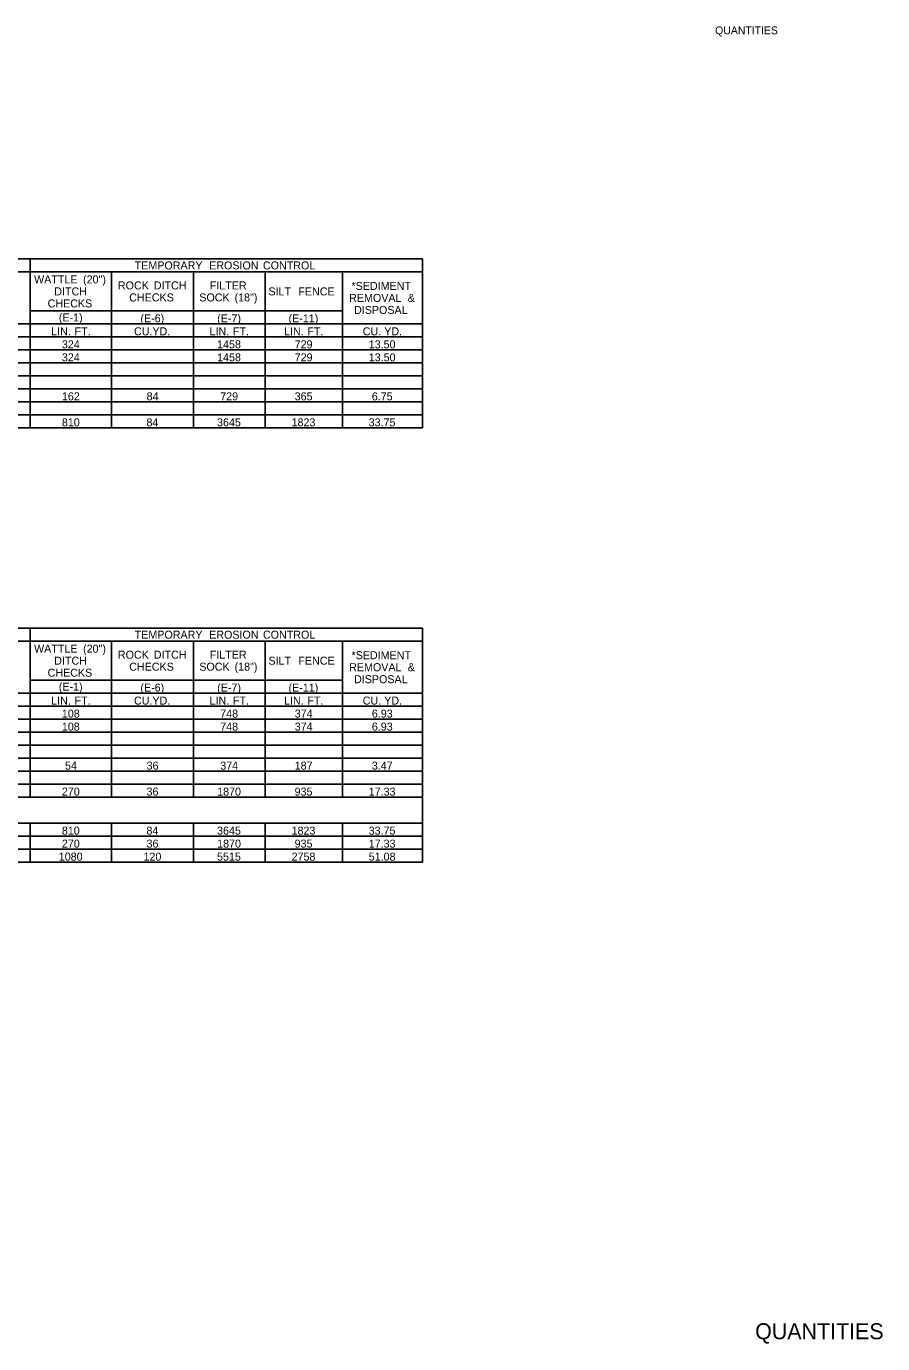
# Model space of a CAD drawing. Extents: x 544478 to 1930787, y -1948294 to 596640.
# Drawn here: x 545147 to 545789, y -1948294 to -1947306 of the extents above; entities that cross this region are included whole.
import ezdxf

# ---------------------------------------------------------------- set-up
doc = ezdxf.new("R2010")
doc.units = 0
for name, color, linetype in [('Default', 7, 'Continuous'), ('R_Border', 7, 'Continuous'), ('R_Border Prem', 7, 'Continuous')]:
    doc.layers.add(name, color=color, linetype=linetype)

msp = doc.modelspace()

# ---------------------------------------------------------------- linework, layer by layer
at = {"layer": 'Default'}
for p, q in [((544525.83, -1947480.84), (545443.79, -1947480.84)), ((545149.83, -1947490.59), (545149.83, -1947480.84)), ((545149.83, -1947607.59), (545149.83, -1947480.84)), ((545443.79, -1947607.59), (545443.79, -1947480.84)), ((544888.53, -1947490.59), (545443.79, -1947490.59)), ((545210.77, -1947607.59), (545210.77, -1947490.59)), ((545272.19, -1947607.59), (545272.19, -1947490.59)), ((545325.82, -1947607.59), (545325.82, -1947490.59)), ((545383.83, -1947607.59), (545383.83, -1947490.59)), ((545149.83, -1947519.84), (545383.83, -1947519.84)), ((544888.53, -1947529.59), (545383.83, -1947529.59)), ((545149.83, -1947597.84), (545149.83, -1947529.59)), ((545210.77, -1947597.84), (545210.77, -1947529.59)), ((545272.19, -1947597.84), (545272.19, -1947529.59)), ((545325.82, -1947607.59), (545325.82, -1947529.59)), ((545383.83, -1947529.59), (545443.79, -1947529.59)), ((545383.83, -1947607.59), (545383.83, -1947529.59)), ((544525.83, -1947539.34), (545443.79, -1947539.34)), ((545443.79, -1947597.84), (545443.79, -1947539.34)), ((544525.83, -1947549.09), (545443.79, -1947549.09)), ((544525.83, -1947558.84), (545443.79, -1947558.84)), ((544525.83, -1947568.59), (545443.79, -1947568.59)), ((544525.83, -1947578.34), (545443.79, -1947578.34)), ((544525.83, -1947588.09), (545443.79, -1947588.09)), ((544525.83, -1947597.84), (545272.19, -1947597.84)), ((544938.74, -1947597.84), (545149.83, -1947597.84)), ((545149.83, -1947597.84), (545272.19, -1947597.84)), ((545272.19, -1947597.84), (545443.79, -1947597.84)), ((545383.83, -1947597.84), (545443.79, -1947597.84)), ((544525.83, -1947607.59), (545443.79, -1947607.59)), ((544525.83, -1947757.74), (545443.79, -1947757.74)), ((545149.83, -1947767.49), (545149.83, -1947757.74)), ((545149.83, -1947884.49), (545149.83, -1947757.74)), ((545443.79, -1947933.24), (545443.79, -1947757.74)), ((544888.53, -1947767.49), (545443.79, -1947767.49)), ((545210.77, -1947884.49), (545210.77, -1947767.49)), ((545272.19, -1947884.49), (545272.19, -1947767.49)), ((545325.82, -1947884.49), (545325.82, -1947767.49)), ((545383.83, -1947884.49), (545383.83, -1947767.49)), ((545149.83, -1947796.74), (545383.83, -1947796.74)), ((544888.53, -1947806.49), (545383.83, -1947806.49)), ((545149.83, -1947874.74), (545149.83, -1947806.49)), ((545210.77, -1947874.74), (545210.77, -1947806.49)), ((545272.19, -1947874.74), (545272.19, -1947806.49)), ((545325.82, -1947884.49), (545325.82, -1947806.49)), ((545383.83, -1947806.49), (545443.79, -1947806.49)), ((545383.83, -1947884.49), (545383.83, -1947806.49)), ((544525.83, -1947816.24), (545443.79, -1947816.24)), ((545443.79, -1947874.74), (545443.79, -1947816.24)), ((544525.83, -1947825.99), (545443.79, -1947825.99)), ((544525.83, -1947835.74), (545443.79, -1947835.74)), ((544525.83, -1947845.49), (545443.79, -1947845.49)), ((544525.83, -1947855.24), (545443.79, -1947855.24)), ((544525.83, -1947864.99), (545443.79, -1947864.99)), ((544525.83, -1947874.74), (545272.19, -1947874.74)), ((544938.74, -1947874.74), (545149.83, -1947874.74)), ((545149.83, -1947874.74), (545272.19, -1947874.74)), ((545272.19, -1947874.74), (545443.79, -1947874.74)), ((545383.83, -1947874.74), (545443.79, -1947874.74)), ((544525.83, -1947884.49), (545443.79, -1947884.49)), ((545443.79, -1947903.99), (545443.79, -1947884.49)), ((544525.83, -1947903.99), (545443.79, -1947903.99)), ((544525.83, -1947903.99), (545443.79, -1947903.99)), ((545149.83, -1947933.24), (545149.83, -1947903.99)), ((545210.77, -1947933.24), (545210.77, -1947903.99)), ((545272.19, -1947933.24), (545272.19, -1947903.99)), ((545325.82, -1947933.24), (545325.82, -1947903.99)), ((545383.83, -1947933.24), (545383.83, -1947903.99)), ((544525.83, -1947913.74), (545443.79, -1947913.74)), ((545149.83, -1947933.24), (545149.83, -1947913.74)), ((545210.77, -1947933.24), (545210.77, -1947913.74)), ((545272.19, -1947933.24), (545272.19, -1947913.74)), ((545325.82, -1947933.24), (545325.82, -1947913.74)), ((545383.83, -1947933.24), (545383.83, -1947913.74)), ((545443.79, -1947933.24), (545443.79, -1947913.74)), ((544525.83, -1947923.49), (545443.79, -1947923.49)), ((544525.83, -1947933.24), (545443.79, -1947933.24))]:
    msp.add_line(p, q, dxfattribs=at)

# ---------------------------------------------------------------- texts
for s, p in [('TEMPORARY', (545228.09, -1947488.71)), (' EROSION', (545281.68, -1947488.71)), (' CONTROL', (545322, -1947488.71)), ('WATTLE', (545152.66, -1947499.21)), (' (20")', (545187.17, -1947499.21)), ('DITCH', (545167.81, -1947508.21)), ('ROCK', (545215.49, -1947503.71)), ('CHECKS', (545223.98, -1947512.71)), (' DITCH', (545240.17, -1947503.71)), ('SOCK', (545276.51, -1947512.71)), ('FILTER', (545284.35, -1947503.71)), (' (18")', (545300.72, -1947512.71)), ('SILT', (545328.33, -1947508.21)), ('  FENCE', (545346.32, -1947508.21)), ('*SEDIMENT', (545390.6, -1947504.09)), ('CHECKS', (545162.8, -1947517.21)), ('REMOVAL', (545388.85, -1947513.09)), ('DISPOSAL', (545392.5, -1947522.09)), (' &', (545430.52, -1947513.09)), ('(E-1)', (545171.2, -1947527.71)), ('(E-6)', (545232.38, -1947528.39)), ('(E-7)', (545289.91, -1947528.39)), ('(E-11)', (545343.4, -1947528.39)), ('LIN.', (545165.51, -1947538.14)), (' FT.', (545180.76, -1947538.14)), ('CU.YD.', (545227.56, -1947538.14)), ('LIN.', (545284.21, -1947538.14)), (' FT.', (545299.47, -1947538.14)), ('LIN.', (545340.03, -1947538.14)), (' FT.', (545355.29, -1947538.14)), ('CU.', (545399.01, -1947538.14)), (' YD.', (545412.88, -1947538.14)), ('324', (545173.51, -1947547.89)), ('1458', (545289.87, -1947547.89)), ('729', (545348.02, -1947547.89)), ('13.50', (545403.53, -1947547.89)), ('324', (545173.51, -1947557.64)), ('1458', (545289.87, -1947557.64)), ('729', (545348.02, -1947557.64)), ('13.50', (545403.53, -1947557.64)), ('162', (545173.53, -1947586.89)), ('84', (545237.02, -1947586.89)), ('729', (545292.2, -1947586.89)), ('365', (545348, -1947586.89)), ('6.75', (545405.82, -1947586.89)), ('810', (545173.51, -1947606.39)), ('84', (545236.91, -1947606.39)), ('3645', (545289.81, -1947606.39)), ('1823', (545345.68, -1947606.39)), ('33.75', (545403.45, -1947606.39)), ('TEMPORARY', (545228.09, -1947765.61)), (' EROSION', (545281.68, -1947765.61)), (' CONTROL', (545322, -1947765.61)), ('WATTLE', (545152.66, -1947776.11)), (' (20")', (545187.17, -1947776.11)), ('DITCH', (545167.81, -1947785.11)), ('ROCK', (545215.49, -1947780.61)), (' DITCH', (545240.17, -1947780.61)), ('FILTER', (545284.35, -1947780.61)), (' (18")', (545300.72, -1947789.61)), ('SILT', (545328.33, -1947785.11)), ('  FENCE', (545346.32, -1947785.11)), ('*SEDIMENT', (545390.6, -1947780.99)), ('CHECKS', (545162.8, -1947794.11)), ('CHECKS', (545223.98, -1947789.61)), ('SOCK', (545276.51, -1947789.61)), ('REMOVAL', (545388.85, -1947789.99)), ('DISPOSAL', (545392.5, -1947798.99)), (' &', (545430.52, -1947789.99)), ('(E-1)', (545171.2, -1947804.61)), ('(E-6)', (545232.38, -1947805.29)), ('(E-7)', (545289.91, -1947805.29)), ('(E-11)', (545343.4, -1947805.29)), ('LIN.', (545165.51, -1947815.04)), (' FT.', (545180.76, -1947815.04)), ('CU.YD.', (545227.56, -1947815.04)), ('LIN.', (545284.21, -1947815.04)), (' FT.', (545299.47, -1947815.04)), ('LIN.', (545340.03, -1947815.04)), (' FT.', (545355.29, -1947815.04)), ('CU.', (545399.01, -1947815.04)), (' YD.', (545412.88, -1947815.04)), ('108', (545173.49, -1947824.79)), ('748', (545292.2, -1947824.79)), ('374', (545348.03, -1947824.79)), ('6.93', (545405.84, -1947824.79)), ('108', (545173.49, -1947834.54)), ('748', (545292.2, -1947834.54)), ('374', (545348.03, -1947834.54)), ('6.93', (545405.84, -1947834.54)), ('54', (545175.84, -1947863.79)), ('36', (545237.01, -1947863.79)), ('374', (545292.22, -1947863.79)), ('187', (545348.02, -1947863.79)), ('3.47', (545405.84, -1947863.79)), ('270', (545173.51, -1947883.29)), ('36', (545236.97, -1947883.29)), ('1870', (545289.89, -1947883.29)), ('935', (545347.96, -1947883.29)), ('17.33', (545403.51, -1947883.29)), ('810', (545173.51, -1947912.54)), ('84', (545236.91, -1947912.54)), ('3645', (545289.81, -1947912.54)), ('1823', (545345.68, -1947912.54)), ('33.75', (545403.45, -1947912.54)), ('270', (545173.51, -1947922.29)), ('36', (545236.97, -1947922.29)), ('1870', (545289.89, -1947922.29)), ('935', (545347.96, -1947922.29)), ('17.33', (545403.51, -1947922.29)), ('1080', (545171.18, -1947932.04)), ('120', (545234.69, -1947932.04)), ('5515', (545289.81, -1947932.04)), ('2758', (545345.69, -1947932.04)), ('51.08', (545403.51, -1947932.04))]:
    msp.add_text(s, height=6, dxfattribs=at).set_placement(p)
at = {"layer": 'R_Border'}
msp.add_text('QUANTITIES', height=12, rotation=360, dxfattribs=at).set_placement((545693.16, -1948290.95))
at = {"layer": 'R_Border Prem'}
msp.add_text('QUANTITIES', height=5.862, rotation=360, dxfattribs=at).set_placement((545663.18, -1947312.39))

doc.saveas('drawing.dxf')
